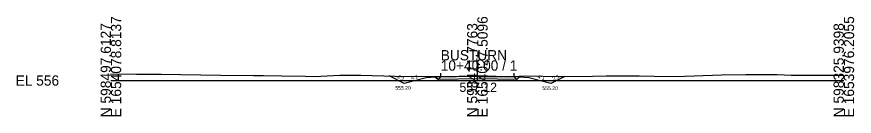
# Model space of a CAD drawing. Extents: x -26 to 1403, y -10 to 2017.
# Drawn here: x -25.7 to 202.8, y 1490.3 to 1517.3 of the extents above; entities that cross this region are included whole.
import ezdxf

# ---------------------------------------------------------------- set-up
doc = ezdxf.new("R2010")
doc.units = 0
for name, color, linetype in [('Exist Cross Section Cell', 7, 'Continuous'), ('Exist XS Center Line Elevation Label', 7, 'Continuous'), ('Exist XS Ground Line', 7, 'Continuous'), ('Prop XS Ditch Slope Text', 7, 'Continuous'), ('Prop XS Earthwork Shape', 7, 'Continuous'), ('Prop XS EOT Tick Mark', 7, 'Continuous'), ('Prop XS Finish Grade', 7, 'Continuous'), ('Prop XS Finish Grade Earthwork', 7, 'Continuous'), ('Prop XS Finish Grade Pavement', 7, 'Continuous'), ('Prop XS Pvmt Edge Slope', 7, 'Continuous'), ('Prop XS Subgrade Earthwork', 7, 'Continuous')]:
    doc.layers.add(name, color=color, linetype=linetype)

msp = doc.modelspace()

# ---------------------------------------------------------------- linework, layer by layer
at = {"layer": 'Exist Cross Section Cell'}
for p, q in [((100, 1500), (100, 1505.48)), ((0, 1500), (100, 1500)), ((100, 1500), (200, 1500))]:
    msp.add_line(p, q, dxfattribs=at)
at = {"layer": 'Exist XS Ground Line'}
for p, q in [((0, 1501.83), (6.98, 1501.73)), ((6.98, 1501.73), (9.45, 1501.69)), ((9.45, 1501.69), (13.68, 1501.69)), ((13.68, 1501.69), (29.91, 1501.49)), ((29.91, 1501.49), (38.94, 1501.34)), ((62.44, 1501.44), (68.2, 1501.49)), ((68.2, 1501.49), (77.54, 1501.2)), ((159.17, 1501.27), (166.65, 1501.52)), ((166.65, 1501.52), (173.29, 1501.62)), ((173.29, 1501.62), (181.83, 1501.6)), ((181.83, 1501.6), (185.62, 1501.47)), ((185.62, 1501.47), (200, 1501.43)), ((38.94, 1501.34), (41.66, 1501.35)), ((41.66, 1501.35), (46.63, 1501.28)), ((46.63, 1501.28), (53.04, 1501.17)), ((53.04, 1501.17), (55.58, 1501.11)), ((55.58, 1501.11), (59.05, 1501.29)), ((59.05, 1501.29), (62.44, 1501.44)), ((77.54, 1501.2), (89.92, 1501.13)), ((89.92, 1501.13), (92.36, 1501.04)), ((92.36, 1501.04), (96.21, 1501.16)), ((96.21, 1501.16), (100, 1501.12)), ((100, 1501.12), (108.22, 1501.02)), ((108.22, 1501.02), (113.06, 1501.27)), ((113.06, 1501.27), (122.75, 1501.11)), ((122.75, 1501.11), (131.4, 1501.16)), ((131.4, 1501.16), (135.15, 1501.27)), ((135.15, 1501.27), (144.11, 1501.24)), ((144.11, 1501.24), (148.23, 1501.22)), ((148.23, 1501.22), (155.39, 1501.11)), ((155.39, 1501.11), (156.5, 1501.17)), ((156.5, 1501.17), (159.17, 1501.27))]:
    msp.add_line(p, q, dxfattribs=at)
at = {"layer": 'Prop XS Earthwork Shape'}
msp.add_lwpolyline([(86, 1500.7), (80, 1499.2), (75.89, 1501.25), (77.54, 1501.2), (89.92, 1501.13), (92.36, 1501.04), (96.21, 1501.16), (100, 1501.12), (108.22, 1501.02), (113.06, 1501.27), (122.75, 1501.11), (123.84, 1501.12), (120, 1499.2), (114, 1500.7), (111.41, 1500.91), (110.73, 1500.26), (100, 1500.47), (89.27, 1500.26), (88.59, 1500.91)], close=True, dxfattribs=at)
at = {"layer": 'Prop XS EOT Tick Mark'}
for p, q in [((90, 1501.02), (90, 1502.02)), ((110, 1501.02), (110, 1502.02))]:
    msp.add_line(p, q, dxfattribs=at)
at = {"layer": 'Prop XS Finish Grade'}
for p, q in [((90, 1501.02), (88.59, 1500.91)), ((111.41, 1500.91), (110, 1501.02))]:
    msp.add_line(p, q, dxfattribs=at)
at = {"layer": 'Prop XS Finish Grade Earthwork'}
for p, q in [((80, 1499.2), (75.89, 1501.25)), ((86, 1500.7), (80, 1499.2)), ((88.59, 1500.91), (86, 1500.7)), ((114, 1500.7), (111.41, 1500.91)), ((120, 1499.2), (114, 1500.7)), ((123.84, 1501.12), (120, 1499.2))]:
    msp.add_line(p, q, dxfattribs=at)
at = {"layer": 'Prop XS Finish Grade Pavement'}
for p, q in [((100, 1501.22), (90, 1501.02)), ((110, 1501.02), (100, 1501.22))]:
    msp.add_line(p, q, dxfattribs=at)
at = {"layer": 'Prop XS Pvmt Edge Slope'}
for p, q in [((89.27, 1500.26), (90, 1501.02)), ((110.73, 1500.26), (110, 1501.02))]:
    msp.add_line(p, q, dxfattribs=at)
at = {"layer": 'Prop XS Subgrade Earthwork'}
for p, q in [((88.59, 1500.91), (89.27, 1500.26)), ((100, 1500.47), (89.27, 1500.26)), ((110.73, 1500.26), (100, 1500.47)), ((111.41, 1500.91), (110.73, 1500.26))]:
    msp.add_line(p, q, dxfattribs=at)

# ---------------------------------------------------------------- texts
at = {"layer": 'Exist Cross Section Cell'}
for s, p in [('N 598497.6127', (0, 1490)), ('E 1654078.8137', (2.8, 1490)), ('N 598411.7763', (100, 1490)), ('E 1654027.5096', (102.8, 1490)), ('N 598325.9398', (200, 1490)), ('E 1653976.2055', (202.8, 1490))]:
    msp.add_text(s, height=2.8, rotation=90, dxfattribs=at).set_placement(p)
for s, p in [('BUSTURN', (90, 1505.48)), ('10+40.00 / 1', (90, 1502.68)), ('EL 556', (-26, 1498.6))]:
    msp.add_text(s, height=2.8, dxfattribs=at).set_placement(p)
at = {"layer": 'Exist XS Center Line Elevation Label'}
msp.add_text('557.12', height=2.5, dxfattribs=at).set_placement((95.12, 1496.91))
at = {"layer": 'Prop XS Ditch Slope Text'}
for s, rotation, p in [('2:1', 333.4349, (78.1, 1500.74)), ('4:1', 14.0362, (82.01, 1500.22)), ('4:1', 345.9638, (116.37, 1500.62)), ('2:1', 26.5651, (120.77, 1499.96))]:
    msp.add_text(s, height=1, rotation=rotation, dxfattribs=at).set_placement(p)
for p in [(77.6, 1497.48), (117.74, 1497.41)]:
    msp.add_text('555.20', height=1, dxfattribs=at).set_placement(p)

doc.saveas('drawing.dxf')
